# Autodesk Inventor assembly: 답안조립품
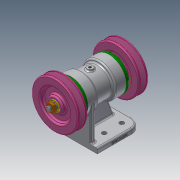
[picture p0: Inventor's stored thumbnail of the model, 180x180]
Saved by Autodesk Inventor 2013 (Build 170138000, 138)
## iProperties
Created: 2020-06
Part Number: 답안조립품
Document SubType Name: Assembly
Designer: 19
Author: 19
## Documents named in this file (12)
- C:\Users\19\Desktop\700606V1038\700606V1038\답안조립품.iam
- C:\Users\19\Desktop\700606V1038\700606V1038\본체.ipt
- C:\Users\19\Desktop\700606V1038\700606V1038\Ű 5x5x12.ipt
- C:\Users\19\Desktop\700606V1038\700606V1038\V-벨트풀리.ipt
- C:\Users\19\Desktop\700606V1038\700606V1038\너트 M10.ipt
- C:\Users\19\Desktop\700606V1038\700606V1038\베어링 6204.ipt
- C:\Users\19\Desktop\700606V1038\700606V1038\볼트 M4.ipt
- C:\Users\19\Desktop\700606V1038\700606V1038\스프링 와셔 10.ipt
- C:\Users\19\Desktop\700606V1038\700606V1038\오일 실 20 32 5.ipt
- C:\Users\19\Desktop\700606V1038\700606V1038\축.ipt
- C:\Users\19\Desktop\700606V1038\700606V1038\커버.ipt
- C:\Users\19\Desktop\700606V1038\700606V1038\평면 와셔 10x21.ipt
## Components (4 placed, 2 different names)
1. Ű 5x5x12:1
2. V-벨트풀리:1
3. V-벨트풀리:2
4. Ű 5x5x12:2
